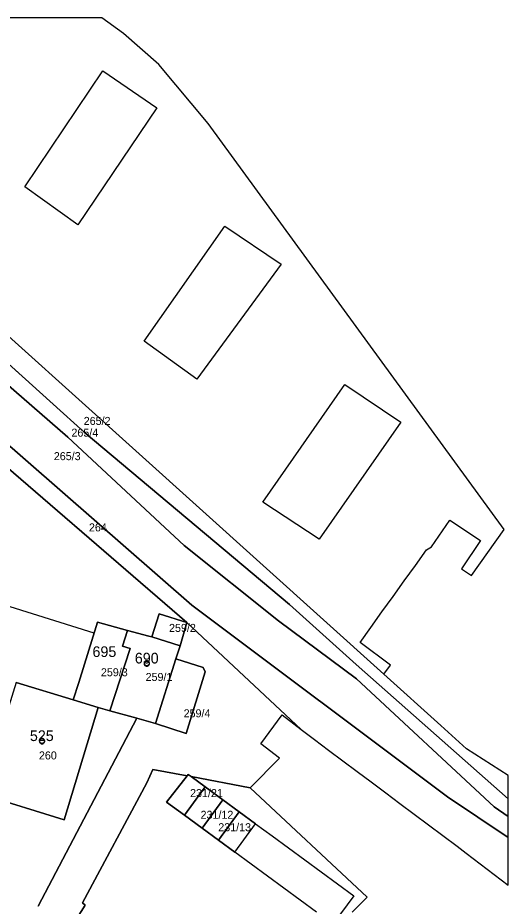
# Model space of a CAD drawing. Extents: x -557590 to -557349, y -1071980 to -1071723.
# Drawn here: x -557440.5 to -557348.7, y -1071889.4 to -1071722.9 of the extents above; entities that cross this region are included whole.
import ezdxf

# ---------------------------------------------------------------- set-up
doc = ezdxf.new("R2010")
doc.units = 0
for name, color, linetype in [('Adresní místo-text', 7, 'Continuous'), ('Parcela-polygon', 7, 'Continuous'), ('Parcela-text', 7, 'Continuous'), ('Stavební objekt-bod', 7, 'Continuous'), ('Stavební objekt-polygon', 7, 'Continuous'), ('Vodovodní přípojka', 7, 'Continuous')]:
    doc.layers.add(name, color=color, linetype=linetype)

msp = doc.modelspace()

# ---------------------------------------------------------------- linework, layer by layer
at = {"layer": 'Parcela-polygon'}
for p, q in [((-557424.8, -1071722.92), (-557491.68, -1071722.92)), ((-557348.7, -1071869.27), (-557348.7, -1071864.9)), ((-557348.7, -1071872.57), (-557348.7, -1071869.27)), ((-557348.7, -1071876.49), (-557348.7, -1071872.57)), ((-557348.7, -1071885.41), (-557348.7, -1071876.49))]:
    msp.add_line(p, q, dxfattribs=at)
for points in [[(-557532.39, -1071722.92), (-557523.38, -1071731.14), (-557519.56, -1071737.83), (-557514.49, -1071741.25), (-557511.78, -1071743.08), (-557507.48, -1071745.99), (-557505.88, -1071747.39), (-557407.94, -1071832.97), (-557360.07, -1071868.88), (-557348.7, -1071876.49)], [(-557348.7, -1071872.57), (-557351.33, -1071870.74), (-557377.12, -1071846.76), (-557391.72, -1071835.9), (-557409.36, -1071821.76), (-557431.2, -1071801.51), (-557454.84, -1071780.92), (-557478.14, -1071758.52), (-557494.89, -1071744.04), (-557501.25, -1071740.35), (-557502.97, -1071739.3), (-557506.49, -1071737.04), (-557509.88, -1071734.87), (-557511.32, -1071733.56), (-557512.83, -1071730.19), (-557520.69, -1071722.92)], [(-557491.68, -1071722.92), (-557494.66, -1071727.17), (-557498.21, -1071732.24), (-557371.98, -1071845.92), (-557370.78, -1071844.22), (-557376.44, -1071839.94), (-557374.45, -1071837.16), (-557372.36, -1071834.24), (-557370.27, -1071831.33), (-557368.18, -1071828.42), (-557366.09, -1071825.51), (-557364, -1071822.6), (-557363.05, -1071822.01), (-557359.61, -1071817.07), (-557353.89, -1071820.86), (-557357.44, -1071826.15), (-557355.59, -1071827.4), (-557349.46, -1071818.81), (-557404.92, -1071742.72), (-557414.14, -1071731.67), (-557420.72, -1071725.86), (-557424.8, -1071722.92)], [(-557348.7, -1071864.9), (-557356.49, -1071859.88), (-557361.34, -1071855.51), (-557371.98, -1071845.92), (-557498.21, -1071732.24), (-557498.56, -1071732.08), (-557498.84, -1071732.98), (-557501.22, -1071736.7), (-557499.68, -1071737.96), (-557465.81, -1071765.76), (-557446.72, -1071782.19), (-557447.53, -1071783.1), (-557428.12, -1071800.58), (-557389.66, -1071832.85), (-557377.15, -1071844.11), (-557348.7, -1071869.27)], [(-557424.6, -1071732.89), (-557414.48, -1071739.81), (-557429.3, -1071761.74), (-557439.23, -1071754.57), (-557424.6, -1071732.89)], [(-557348.7, -1071869.27), (-557377.15, -1071844.11), (-557389.66, -1071832.85), (-557428.12, -1071800.58), (-557447.53, -1071783.1), (-557446.72, -1071782.19), (-557465.81, -1071765.76), (-557499.68, -1071737.96), (-557501.22, -1071736.7), (-557503.91, -1071734.49), (-557506.49, -1071737.04), (-557502.97, -1071739.3), (-557501.25, -1071740.35), (-557494.89, -1071744.04), (-557478.14, -1071758.52), (-557454.84, -1071780.92), (-557431.2, -1071801.51), (-557409.36, -1071821.76), (-557391.72, -1071835.9), (-557377.12, -1071846.76), (-557351.33, -1071870.74), (-557348.7, -1071872.57)], [(-557348.7, -1071876.49), (-557360.07, -1071868.88), (-557407.94, -1071832.97), (-557505.88, -1071747.39), (-557507.48, -1071745.99), (-557509.91, -1071749.02), (-557508.17, -1071750.52), (-557408.88, -1071836.21), (-557387.5, -1071856.25), (-557385.01, -1071858.11), (-557382.34, -1071860.11), (-557379.67, -1071862.11), (-557376.99, -1071864.11), (-557374.36, -1071866.09), (-557371.65, -1071868.11), (-557368.98, -1071870.11), (-557366.31, -1071872.11), (-557363.63, -1071874.12), (-557360.97, -1071876.11), (-557358.29, -1071878.11), (-557356.55, -1071879.44), (-557348.7, -1071885.41)], [(-557440.87, -1071847.45), (-557430.15, -1071850.71), (-557429.13, -1071847.47), (-557425.59, -1071836.18), (-557419.99, -1071837.69), (-557415.99, -1071838.76), (-557415.43, -1071838.93), (-557414.06, -1071834.57), (-557408.88, -1071836.21), (-557508.17, -1071750.52)], [(-557401.8, -1071761.99), (-557391.2, -1071769.06), (-557407.03, -1071790.63), (-557416.86, -1071783.5), (-557401.8, -1071761.99)], [(-557379.3, -1071791.61), (-557368.82, -1071798.67), (-557384.11, -1071820.62), (-557394.64, -1071813.69), (-557379.3, -1071791.61)], [(-557435.73, -1071901.54), (-557427.91, -1071889.15), (-557428.41, -1071888.74), (-557416.38, -1071866.24), (-557415.28, -1071863.73), (-557408.85, -1071864.95), (-557408.65, -1071864.68), (-557408.08, -1071865.09), (-557397.05, -1071867.18), (-557391.52, -1071861.63), (-557395.06, -1071858.98), (-557391.06, -1071853.54), (-557387.5, -1071856.25), (-557408.88, -1071836.21), (-557410.14, -1071840.56), (-557410.93, -1071843.04), (-557405.83, -1071844.64), (-557405.45, -1071845.45), (-557409.01, -1071857.02), (-557414.76, -1071855.12), (-557418.28, -1071854.14), (-557422.96, -1071863.09), (-557436.71, -1071889.39)], [(-557436.71, -1071889.39), (-557422.96, -1071863.09), (-557418.28, -1071854.14), (-557423.28, -1071852.75), (-557425.5, -1071852.13), (-557431.85, -1071873.19), (-557447.24, -1071868.43)], [(-557384.6, -1071890.51), (-557387.66, -1071888.26), (-557390.72, -1071886.01), (-557393.79, -1071883.76), (-557396.85, -1071881.51), (-557399.91, -1071879.27), (-557402.97, -1071877.02), (-557406.03, -1071874.77), (-557409.34, -1071872.34), (-557412.67, -1071869.9), (-557408.85, -1071864.95), (-557415.28, -1071863.73), (-557416.38, -1071866.24), (-557428.41, -1071888.74), (-557427.91, -1071889.15), (-557435.73, -1071901.54)], [(-557377.9, -1071890.5), (-557375.15, -1071887.67), (-557397.05, -1071867.18), (-557408.08, -1071865.09), (-557405.43, -1071867.02), (-557402.13, -1071869.45), (-557399.06, -1071871.7), (-557396, -1071873.95), (-557392.94, -1071876.19), (-557389.88, -1071878.44), (-557386.82, -1071880.69), (-557383.75, -1071882.94), (-557380.69, -1071885.19), (-557377.63, -1071887.44), (-557381.54, -1071892.76)]]:
    msp.add_lwpolyline(points, dxfattribs=at)
for points in [[(-557414.06, -1071834.57), (-557415.43, -1071838.93), (-557410.14, -1071840.56), (-557408.88, -1071836.21)], [(-557425.59, -1071836.18), (-557429.13, -1071847.47), (-557430.15, -1071850.71), (-557425.5, -1071852.13), (-557423.28, -1071852.75), (-557419.48, -1071841.11), (-557420.94, -1071840.64), (-557419.99, -1071837.69)], [(-557420.94, -1071840.64), (-557419.48, -1071841.11), (-557423.28, -1071852.75), (-557418.28, -1071854.14), (-557414.76, -1071855.12), (-557410.93, -1071843.04), (-557410.14, -1071840.56), (-557415.43, -1071838.93), (-557415.99, -1071838.76), (-557419.99, -1071837.69)], [(-557410.93, -1071843.04), (-557414.76, -1071855.12), (-557409.01, -1071857.02), (-557405.45, -1071845.45), (-557405.83, -1071844.64)], [(-557425.5, -1071852.13), (-557430.15, -1071850.71), (-557440.87, -1071847.45), (-557443.01, -1071854.5), (-557444.31, -1071854.11), (-557446.3, -1071861.09), (-557445.12, -1071861.45), (-557447.24, -1071868.43), (-557431.85, -1071873.19)], [(-557408.65, -1071864.68), (-557408.85, -1071864.95), (-557412.67, -1071869.9), (-557409.34, -1071872.34), (-557405.43, -1071867.02), (-557408.08, -1071865.09)], [(-557405.43, -1071867.02), (-557409.34, -1071872.34), (-557406.03, -1071874.77), (-557402.13, -1071869.45)], [(-557402.13, -1071869.45), (-557406.03, -1071874.77), (-557402.97, -1071877.02), (-557399.06, -1071871.7)], [(-557402.97, -1071877.02), (-557399.91, -1071879.27), (-557396, -1071873.95), (-557399.06, -1071871.7)]]:
    msp.add_lwpolyline(points, close=True, dxfattribs=at)
at = {"layer": 'Stavební objekt-bod'}
for points in [[(-557416.4, -1071843.39), (-557416.27, -1071843.39), (-557416.15, -1071843.45), (-557416.04, -1071843.52), (-557415.97, -1071843.64), (-557415.9, -1071843.76), (-557415.9, -1071843.89), (-557415.9, -1071844.02), (-557415.97, -1071844.14), (-557416.03, -1071844.26), (-557416.15, -1071844.32), (-557416.27, -1071844.39), (-557416.4, -1071844.39), (-557416.53, -1071844.39), (-557416.65, -1071844.32), (-557416.77, -1071844.26), (-557416.83, -1071844.14), (-557416.9, -1071844.02), (-557416.9, -1071843.89), (-557416.9, -1071843.76), (-557416.83, -1071843.64), (-557416.77, -1071843.52), (-557416.65, -1071843.45), (-557416.53, -1071843.39), (-557416.4, -1071843.39)], [(-557416.84, -1071843.89), (-557416.84, -1071844), (-557416.78, -1071844.11), (-557416.72, -1071844.21), (-557416.62, -1071844.27), (-557416.51, -1071844.33), (-557416.4, -1071844.33), (-557416.29, -1071844.33), (-557416.18, -1071844.27), (-557416.08, -1071844.21), (-557416.02, -1071844.11), (-557415.96, -1071844), (-557415.96, -1071843.89), (-557415.96, -1071843.78), (-557416.02, -1071843.67), (-557416.08, -1071843.57), (-557416.19, -1071843.51), (-557416.29, -1071843.45), (-557416.4, -1071843.45), (-557416.51, -1071843.45), (-557416.62, -1071843.51), (-557416.72, -1071843.57), (-557416.78, -1071843.67), (-557416.84, -1071843.78), (-557416.84, -1071843.89)], [(-557436.01, -1071857.93), (-557435.88, -1071857.93), (-557435.76, -1071857.99), (-557435.65, -1071858.06), (-557435.58, -1071858.18), (-557435.51, -1071858.3), (-557435.51, -1071858.43), (-557435.51, -1071858.56), (-557435.58, -1071858.68), (-557435.64, -1071858.8), (-557435.76, -1071858.86), (-557435.88, -1071858.93), (-557436.01, -1071858.93), (-557436.14, -1071858.93), (-557436.26, -1071858.86), (-557436.38, -1071858.8), (-557436.44, -1071858.68), (-557436.51, -1071858.56), (-557436.51, -1071858.43), (-557436.51, -1071858.3), (-557436.44, -1071858.18), (-557436.38, -1071858.06), (-557436.26, -1071857.99), (-557436.14, -1071857.93), (-557436.01, -1071857.93)], [(-557436.45, -1071858.43), (-557436.45, -1071858.54), (-557436.39, -1071858.65), (-557436.33, -1071858.75), (-557436.23, -1071858.81), (-557436.12, -1071858.87), (-557436.01, -1071858.87), (-557435.9, -1071858.87), (-557435.79, -1071858.81), (-557435.69, -1071858.75), (-557435.63, -1071858.65), (-557435.57, -1071858.54), (-557435.57, -1071858.43), (-557435.57, -1071858.32), (-557435.63, -1071858.21), (-557435.69, -1071858.11), (-557435.8, -1071858.05), (-557435.9, -1071857.99), (-557436.01, -1071857.99), (-557436.12, -1071857.99), (-557436.23, -1071858.05), (-557436.33, -1071858.11), (-557436.39, -1071858.21), (-557436.45, -1071858.32), (-557436.45, -1071858.43)]]:
    msp.add_open_spline(points, degree=3, dxfattribs=at)
at = {"layer": 'Stavební objekt-polygon'}
for points in [[(-557410.93, -1071843.04), (-557410.14, -1071840.56), (-557415.43, -1071838.93), (-557415.99, -1071838.76), (-557419.99, -1071837.69), (-557425.59, -1071836.18), (-557429.13, -1071847.47), (-557430.15, -1071850.71), (-557425.5, -1071852.13), (-557423.28, -1071852.75), (-557418.28, -1071854.14), (-557414.76, -1071855.12)], [(-557425.5, -1071852.13), (-557430.15, -1071850.71), (-557440.87, -1071847.45), (-557443.01, -1071854.5), (-557444.31, -1071854.11), (-557446.3, -1071861.09), (-557445.12, -1071861.45), (-557447.24, -1071868.43), (-557431.85, -1071873.19)]]:
    msp.add_lwpolyline(points, close=True, dxfattribs=at)
at = {"layer": 'Vodovodní přípojka'}
msp.add_lwpolyline([(-557426.24, -1071838.24), (-557445.22, -1071832.28), (-557445.33, -1071832.25)], dxfattribs=at)

# ---------------------------------------------------------------- texts
at = {"layer": 'Adresní místo-text'}
for s, p in [('695', (-557426.56, -1071842.68)), ('690', (-557418.63, -1071843.89)), ('525', (-557438.28, -1071858.43))]:
    msp.add_text(s, height=2, dxfattribs=at).set_placement(p)
at = {"layer": 'Parcela-text'}
for s, p in [('265/2', (-557428.2, -1071799.2)), ('265/4', (-557430.5, -1071801.4)), ('265/3', (-557433.8, -1071805.8)), ('264', (-557427.22, -1071819.15)), ('259/2', (-557412.22, -1071837.98)), ('259/3', (-557424.98, -1071846.29)), ('259/1', (-557416.61, -1071847.17)), ('259/4', (-557409.49, -1071853.98)), ('260', (-557436.59, -1071861.87)), ('231/21', (-557408.28, -1071868.92)), ('231/12', (-557406.32, -1071872.99)), ('231/13', (-557403, -1071875.32))]:
    msp.add_text(s, height=1.5, dxfattribs=at).set_placement(p)

doc.saveas('drawing.dxf')
